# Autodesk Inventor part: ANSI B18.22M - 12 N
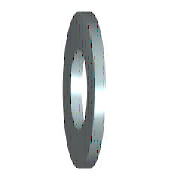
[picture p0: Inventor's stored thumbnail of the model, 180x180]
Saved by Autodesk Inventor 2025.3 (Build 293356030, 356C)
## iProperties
IsCustomPart: 0
Created: 2024-01
Part Number: ANSI B18.22M - 12 N
Material: Acero, suave
Description: Arandelas métricas planas
Document SubType Name: Modeling
Standard: ANSI B18.22M
Designer: User
Standard Revision: 2005
Standards Organization: ANSI
Language: es-ES
Size Designation: 12 N
Categories: <MemberInstance><Categories><Category DisplayName="Fijaciones" InternalName="e4da775c-781d-43d5-af7c-5136215cf5a6" Mnemonic="FSTN"><Category DisplayName="Arande
Density: 7.85 g/cm^3
Appearance: Semipulido
Author: User
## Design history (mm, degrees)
body "Solid1"
sketch "Boceto"
  geometry: C1 r 12.7 at (0, 0); C2 r 6.65 at (0, 0); 1 further point
  constraints: 2 centre point, 2 coincident
  dimensions: "d0" = 13.3 diameter of C2 (= SD1); "d1" = 25.4 diameter of C1 (= SD2)
extrude "Cuerpo" new body sketch "Boceto" distance "d2" = 2.8 (= SD); taper "d3" = 0 deg
workaxis "Work Axis1"
workplane "Work Plane1"
other parameters: "SD1" = 13.3 [user parameter; used in 1 equation term], "SD2" = 25.4 [user parameter; used in 1 equation term], "SD" = 2.8 [user parameter; used in 1 equation term], "d4" = 0, "d5" = 0, "d6" = 0, "d7" = 0, "NND" = 12 [user parameter]
